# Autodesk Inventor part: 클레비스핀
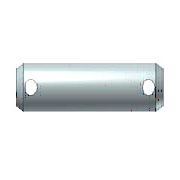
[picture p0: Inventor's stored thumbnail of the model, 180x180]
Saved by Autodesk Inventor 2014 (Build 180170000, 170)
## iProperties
IsCustomPart: 1
Created: 2012-02
Part Number: 클레비스핀
Material: 강철
Description: 머리가 없는 클레비스 핀 B
Document SubType Name: Modeling
Standard: ISO 2340
Designer: mduedu
Standard Revision: Second edition 1986-11-01
Standards Organization: ISO
Language: ko-KR
Size Designation: B - 8 x 45
Categories: <MemberInstance><Categories><Category DisplayName="조임쇠" InternalName="e4da775c-781d-43d5-af7c-5136215cf5a6" Mnemonic="FSTN"><Category DisplayName="핀" InternalNa
Density: 7.85 g/cm^3
Appearance: 강철
Author: mduedu
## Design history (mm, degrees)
sketch "스케치1"
  geometry: L1 (-4.5, 0)-(-4.5, 4); L2 (-4.5, 4)-(40.5, 4); L3 (40.5, 4)-(40.5, 0); L4 (-4.5, 0)-(40.5, 0); L5 (0, -1.46)-(0, 3.16) reference; L6 (-6.4, 0)-(18.8, 0) reference; C1 r 1 at (-1, 0); C2 r 1 at (37, 0)
  constraints: 8 end point, 2 centre point, 2 perpendicular, 2 point on line, 1 collinear, 1 parallel, 1 tangent, 1 vertical
  dimensions: "d0" = 8 diameter of L2 L4 (= NND); "d1" = 45 distance of L1.end L2.end (= NLG); "d2" = 3.5 distance from line of L1 C1.centre (= DIST1); "d3" = 3.5 distance from line of L3 C2.centre (= DIST2); "d4" = 2 diameter of C1 (= BOR1); "d5" = 2 diameter of C2 (= BOR2)
revolve "본체" stored, may be unused: angle "d7" = 90 deg
extrude "구멍1" cut sketch "스케치1" taper "d6" = 0 deg; stored distance "d8" = 10
extrude "구멍2" cut sketch "스케치1" taper "d13" = 0 deg; stored distance "d14" = 10
workaxis "Work Axis1"
workaxis "Work Axis2"
workplane "Work Plane1"
node "작업 평면5"
body "Solid1"
chamfer "모따기2" distance "d9" = 2 (= PHH2); stored, may be unused: angle "d10" = 30 deg (= FAWI2), second distance "d40" = 2 (= PHH2)
chamfer "모따기1" distance "d11" = 2 (= PHH1); stored, may be unused: angle "d12" = 30 deg (= FAWI1), second distance "d41" = 2 (= PHH1)
other parameters: "NLG" = 45 [user parameter; used in 1 equation term], "NND" = 8 [user parameter; used in 1 equation term], "PHH1" = 2 [user parameter; used in 3 equation terms], "PHH2" = 2 (= PHH1) [user parameter; used in 2 equation terms], "FAWI1" = 30 deg [user parameter; used in 1 equation term], "FAWI2" = 30 deg [user parameter; used in 1 equation term], "DIST1" = 3.5 [user parameter; used in 4 equation terms], "DIST2" = 3.5 (= DIST1) [user parameter; used in 1 equation term], "BOR1" = 2 [user parameter; used in 4 equation terms], "BOR2" = 2 (= BOR1) [user parameter; used in 1 equation term], "d15" = 0, "d42" = 0, "d43" = 0, "d44" = -4.5 (= -0.5 x BOR1 - DIST1), "d45" = -4.5 (= -0.5 x BOR1 - DIST1), "d47" = 0, "d48" = 0, "d49" = 0, "d50" = 0, "d51" = 0, "d52" = 0
